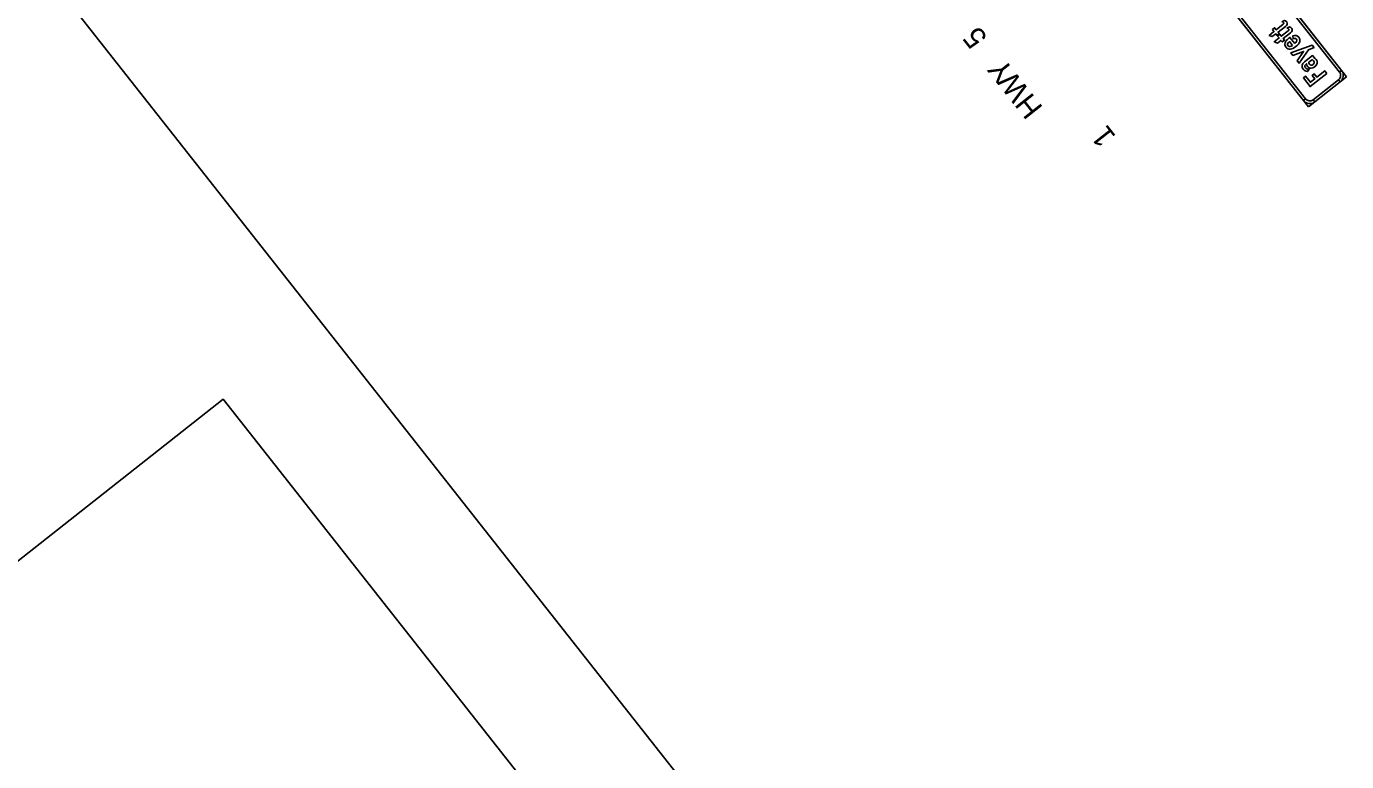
# Model space of a CAD drawing. Extents: x 672239 to 673995, y 1673540 to 1675195.
# Drawn here: x 673278.8 to 673767.4, y 1674177 to 1674449 of the extents above; entities that cross this region are included whole.
import ezdxf

# ---------------------------------------------------------------- set-up
doc = ezdxf.new("R2010")
doc.units = 0
doc.layers.add('C-ANNO-SYMB', color=7, linetype='Continuous')
doc.layers.add('C-HELI-DIST', color=7, linetype='Continuous')

msp = doc.modelspace()

# ---------------------------------------------------------------- linework, layer by layer
at = {"layer": 'C-ANNO-SYMB'}
for p, q in [((673726.5, 1674482.2), (673767.36, 1674430.37)), ((673712.36, 1674471.06), (673753.22, 1674419.23)), ((673753.22, 1674419.23), (673767.36, 1674430.37)), ((673764.38, 1674429.3), (673765, 1674428.51)), ((673765.5, 1674432.73), (673764.72, 1674432.11)), ((673752.15, 1674422.2), (673751.37, 1674421.58)), ((673755.58, 1674421.08), (673754.96, 1674421.87))]:
    msp.add_line(p, q, dxfattribs=at)
for points in [[(673764.72, 1674432.11), (673727.57, 1674479.23), (673728.36, 1674479.85), (673765.5, 1674432.73), (673764.72, 1674432.11), (673764.72, 1674432.11)], [(673715.01, 1674469.32), (673752.15, 1674422.2), (673751.37, 1674421.58), (673714.22, 1674468.7), (673715.01, 1674469.32), (673715.01, 1674469.32)], [(673743.42, 1674450.7), (673743.83, 1674450.56), (673744.07, 1674450.39), (673744.14, 1674450.11), (673743.89, 1674449.8), (673741.31, 1674447.76), (673740.73, 1674448.5), (673739.91, 1674447.85), (673740.49, 1674447.12), (673738.71, 1674445.71), (673739.87, 1674445.22), (673741.17, 1674446.25), (673741.63, 1674445.66), (673742.45, 1674446.31), (673741.99, 1674446.89), (673744.73, 1674449.04), (673745.09, 1674449.4), (673745.32, 1674449.78), (673745.37, 1674450.25), (673745.18, 1674450.68), (673744.8, 1674451.05), (673744.38, 1674451.24)], [(673745.3, 1674448.31), (673745.72, 1674448.18), (673745.95, 1674448.01), (673746.02, 1674447.72), (673745.77, 1674447.41), (673743.19, 1674445.37), (673742.61, 1674446.11), (673741.79, 1674445.46), (673742.37, 1674444.73), (673740.59, 1674443.33), (673741.75, 1674442.83), (673743.06, 1674443.86), (673743.52, 1674443.28), (673744.34, 1674443.92), (673743.88, 1674444.5), (673746.61, 1674446.66), (673746.98, 1674447.01), (673747.2, 1674447.4), (673747.26, 1674447.86), (673747.06, 1674448.29), (673746.68, 1674448.66), (673746.26, 1674448.85)], [(673755.39, 1674441.21), (673754.59, 1674442.1), (673746.75, 1674439.24), (673747.49, 1674438.3), (673751.41, 1674439.77), (673749.09, 1674436.28), (673749.79, 1674435.39), (673753.2, 1674440.4)], [(673760.01, 1674431.62), (673759.29, 1674432.53), (673756.36, 1674430.22), (673755.38, 1674431.45), (673754.57, 1674430.81), (673755.55, 1674429.58), (673753.98, 1674428.34), (673752.19, 1674430.6), (673751.35, 1674429.93), (673753.84, 1674426.77)], [(673754.96, 1674421.87), (673764.38, 1674429.3), (673765, 1674428.51), (673755.58, 1674421.08), (673754.96, 1674421.87), (673754.96, 1674421.87)], [(673608.64, 1673984.97), (673351.55, 1674311.09), (673174.58, 1674171.58), (673431.68, 1673845.46)]]:
    msp.add_lwpolyline(points, close=True, dxfattribs=at)
for points in [[(673748.17, 1674442.67), (673746.36, 1674444.95), (673745.94, 1674444.62), (673745.44, 1674444.18), (673745.04, 1674443.75), (673744.76, 1674443.32), (673744.58, 1674442.9), (673744.51, 1674442.49), (673744.55, 1674442.08), (673744.7, 1674441.67), (673744.95, 1674441.27), (673745.29, 1674440.93), (673745.65, 1674440.7), (673746.06, 1674440.58), (673746.5, 1674440.56), (673746.98, 1674440.66), (673747.49, 1674440.86), (673748.04, 1674441.17), (673748.62, 1674441.6), (673749.14, 1674442.05), (673749.55, 1674442.49), (673749.85, 1674442.92), (673750.03, 1674443.35), (673750.11, 1674443.77), (673750.07, 1674444.18), (673749.93, 1674444.59), (673749.67, 1674444.99), (673749.22, 1674445.42), (673748.71, 1674445.65), (673748.13, 1674445.7), (673747.49, 1674445.56), (673747.53, 1674444.48), (673748.2, 1674444.6), (673748.56, 1674444.53), (673748.82, 1674444.32), (673748.96, 1674443.92), (673748.8, 1674443.42), (673748.54, 1674443.03), (673748.17, 1674442.67)], [(673747.34, 1674441.97), (673746.82, 1674441.65), (673746.37, 1674441.52), (673745.99, 1674441.59), (673745.68, 1674441.84), (673745.51, 1674442.2), (673745.54, 1674442.58), (673745.78, 1674442.98), (673746.21, 1674443.4), (673747.34, 1674441.97)], [(673755.42, 1674437.44), (673754.78, 1674438.25), (673751.78, 1674435.88), (673751.2, 1674435.29), (673750.91, 1674434.65), (673750.88, 1674434.28), (673750.93, 1674433.92), (673751.08, 1674433.56), (673751.31, 1674433.21), (673751.64, 1674432.87), (673752, 1674432.6), (673752.4, 1674432.42), (673752.84, 1674432.3), (673753.5, 1674433.18), (673753.07, 1674433.18), (673752.69, 1674433.27), (673752.36, 1674433.45), (673752.09, 1674433.71), (673751.87, 1674434.15), (673751.94, 1674434.53), (673752.56, 1674435.18), (673752.65, 1674434.64), (673752.86, 1674434.22), (673753.15, 1674433.93), (673753.45, 1674433.71), (673753.8, 1674433.58), (673754.17, 1674433.52), (673754.89, 1674433.65), (673755.6, 1674434.06), (673756.14, 1674434.64), (673756.44, 1674435.34), (673756.5, 1674435.74), (673756.47, 1674436.1), (673756.35, 1674436.45), (673756.14, 1674436.77), (673755.71, 1674437.19), (673755.3, 1674437.34), (673755.42, 1674437.44)], [(673753.37, 1674435.82), (673754.31, 1674436.57), (673754.51, 1674436.67), (673754.71, 1674436.66), (673754.91, 1674436.55), (673755.12, 1674436.33), (673755.33, 1674435.96), (673755.37, 1674435.59), (673755.25, 1674435.23), (673754.96, 1674434.92), (673754.58, 1674434.7), (673754.23, 1674434.63), (673753.91, 1674434.74), (673753.62, 1674435), (673753.43, 1674435.37), (673753.37, 1674435.82)]]:
    msp.add_lwpolyline(points, dxfattribs=at)
for centre, radius, start, end in [((673763.15, 1674430.87), 2, 308.2504, 38.2506), ((673763.15, 1674430.87), 3, 308.2504, 38.2506), ((673753.72, 1674423.44), 3, 218.2508, 308.2504), ((673753.72, 1674423.44), 2, 218.2508, 308.2504)]:
    msp.add_arc(centre, radius, start, end, dxfattribs=at)
at = {"layer": 'C-HELI-DIST'}
msp.add_lwpolyline([(673177.78, 1673539.85), (672546.3, 1674340.87), (673064.6, 1674749.47), (673696.09, 1673948.45)], close=True, dxfattribs=at)

# ---------------------------------------------------------------- texts
at = {"layer": 'C-ANNO-SYMB'}
for s, p in [('5', (673634.74, 1674444.93)), ('Y', (673644.69, 1674432.3)), ('W', (673650.34, 1674425.14)), ('H', (673655.24, 1674418.92)), ('1', (673682.25, 1674408.29))]:
    msp.add_text(s, height=8, rotation=128.2505, dxfattribs=at).set_placement(p)

doc.saveas('drawing.dxf')
